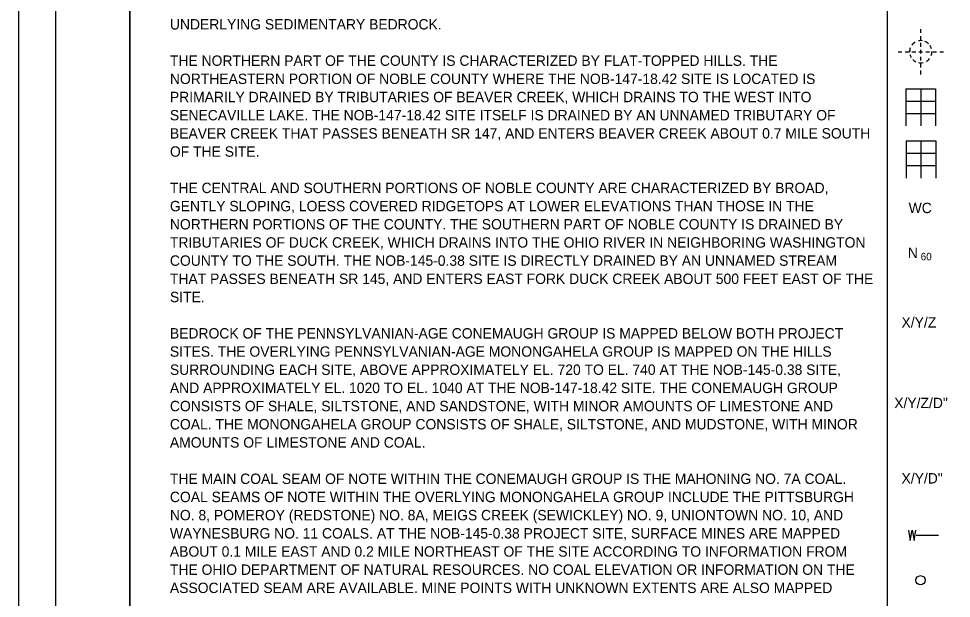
# Model space of a CAD drawing. Extents: x 0 to 34, y -8.9 to 22.
# Drawn here: x 0 to 12.57, y 6.5 to 14.31 of the extents above; entities that cross this region are included whole.
import ezdxf

# ---------------------------------------------------------------- set-up
doc = ezdxf.new("R2010")
doc.units = 0
for name, color, linetype in [('Default', 7, 'Continuous'), ('GT_Historic_Soil_Boring', 7, 'Continuous'), ('GT_Project_Cells', 7, 'Continuous'), ('GT_Project_Soil_Boring', 7, 'Continuous'), ('SH_Border', 7, 'Continuous'), ('SH_Cut_Line', 7, 'Continuous'), ('SH_Data', 7, 'Continuous'), ('SH_Text', 7, 'Continuous')]:
    doc.layers.add(name, color=color, linetype=linetype)

msp = doc.modelspace()

# ---------------------------------------------------------------- linework, layer by layer
at = {"layer": 'Default'}
for p, q in [((11.956, 12.663), (12.356, 12.663)), ((11.956, 12.663), (11.956, 12.163)), ((12.156, 12.663), (12.156, 12.163)), ((12.356, 12.663), (12.356, 12.163))]:
    msp.add_line(p, q, dxfattribs=at)
at = {"layer": 'GT_Historic_Soil_Boring'}
for p, q in [((12.154, 14.12), (12.154, 14.17)), ((12.154, 14.027), (12.154, 14.077)), ((12.154, 13.933), (12.154, 13.983)), ((11.849, 13.865), (11.899, 13.865)), ((11.943, 13.865), (11.993, 13.865)), ((12.036, 13.865), (12.086, 13.865)), ((12.129, 13.865), (12.179, 13.865)), ((12.154, 13.84), (12.154, 13.89)), ((12.223, 13.865), (12.273, 13.865)), ((12.316, 13.865), (12.366, 13.865)), ((12.409, 13.865), (12.459, 13.865)), ((12.154, 13.747), (12.154, 13.797)), ((12.154, 13.653), (12.154, 13.703)), ((12.154, 13.56), (12.154, 13.61))]:
    msp.add_line(p, q, dxfattribs=at)
for start, end in [(119.8468, 142.879), (80.7068, 102.4607), (46.3828, 68.4543), (160.0066, 182.1314), (194.7234, 210.6686), (15.179, 33.755), (339.9977, 1.8728), (224.4987, 243.6713), (257.8817, 281.9218), (300.6921, 322.0293)]:
    msp.add_arc((12.154, 13.865), 0.15, start, end, dxfattribs=at)
at = {"layer": 'GT_Project_Cells'}
msp.add_circle((12.151, 6.742), 0.0625, dxfattribs=at)
at = {"layer": 'GT_Project_Soil_Boring'}
for p, q in [((11.954, 13.365), (12.354, 13.365)), ((11.954, 13.365), (11.954, 12.865)), ((12.154, 13.365), (12.154, 12.865)), ((12.354, 13.365), (12.354, 12.865)), ((11.954, 13.198), (12.354, 13.198)), ((11.954, 13.032), (12.354, 13.032)), ((11.956, 12.497), (12.356, 12.497)), ((11.956, 12.33), (12.356, 12.33))]:
    msp.add_line(p, q, dxfattribs=at)
at = {"layer": 'SH_Border'}
for points in [[(0.5, 21.5), (1.5, 21.5), (1.5, 0.5), (0.5, 0.5)], [(1.5, 21.5), (33.5, 21.5), (33.5, 0.5), (1.5, 0.5)]]:
    msp.add_lwpolyline(points, close=True, dxfattribs=at)
at = {"layer": 'SH_Cut_Line'}
msp.add_lwpolyline([(0, 0), (34, 0), (34, 22), (0, 22)], close=True, dxfattribs=at)
at = {"layer": 'SH_Data'}
msp.add_line((11.705, 1.157), (11.705, 21.5), dxfattribs=at)
at = {"layer": 'SH_Text'}
msp.add_line((12.092, 7.349), (12.392, 7.349), dxfattribs=at)
msp.add_lwpolyline([(11.991, 7.419), (12.012, 7.279), (12.039, 7.419), (12.067, 7.279), (12.089, 7.419)], dxfattribs=at)

# ---------------------------------------------------------------- texts
at = {"layer": 'SH_Data'}
for s, height, p in [('WC', 0.14, (11.991, 11.69)), ('N', 0.14, (11.98, 11.085)), ('60', 0.1, (12.153, 11.055)), ('X/Y/Z', 0.14, (11.895, 10.147)), ('X/Y/Z/D"', 0.14, (11.797, 9.062)), ('X/Y/D"', 0.14, (11.895, 8.046))]:
    msp.add_text(s, height=height, dxfattribs=at).set_placement(p)
at = {"layer": 'SH_Text'}
for s, p in [('UNDERLYING SEDIMENTARY BEDROCK.', (2.038, 14.165)), ('THE NORTHERN PART OF THE COUNTY IS CHARACTERIZED BY FLAT-TOPPED HILLS. THE ', (2.038, 13.675)), ('NORTHEASTERN PORTION OF NOBLE COUNTY WHERE THE NOB-147-18.42 SITE IS LOCATED IS ', (2.038, 13.43)), ('PRIMARILY DRAINED BY TRIBUTARIES OF BEAVER CREEK, WHICH DRAINS TO THE WEST INTO ', (2.038, 13.185)), ('SENECAVILLE LAKE. THE NOB-147-18.42 SITE ITSELF IS DRAINED BY AN UNNAMED TRIBUTARY OF ', (2.038, 12.94)), ('BEAVER CREEK THAT PASSES BENEATH SR 147, AND ENTERS BEAVER CREEK ABOUT 0.7 MILE SOUTH ', (2.038, 12.695)), ('OF THE SITE.', (2.038, 12.45)), ('THE CENTRAL AND SOUTHERN PORTIONS OF NOBLE COUNTY ARE CHARACTERIZED BY BROAD, ', (2.038, 11.96)), ('GENTLY SLOPING, LOESS COVERED RIDGETOPS AT LOWER ELEVATIONS THAN THOSE IN THE ', (2.038, 11.715)), ('NORTHERN PORTIONS OF THE COUNTY. THE SOUTHERN PART OF NOBLE COUNTY IS DRAINED BY ', (2.038, 11.47)), ('TRIBUTARIES OF DUCK CREEK, WHICH DRAINS INTO THE OHIO RIVER IN NEIGHBORING WASHINGTON ', (2.038, 11.225)), ('COUNTY TO THE SOUTH. THE NOB-145-0.38 SITE IS DIRECTLY DRAINED BY AN UNNAMED STREAM ', (2.038, 10.98)), ('THAT PASSES BENEATH SR 145, AND ENTERS EAST FORK DUCK CREEK ABOUT 500 FEET EAST OF THE ', (2.038, 10.735)), ('SITE. ', (2.038, 10.49)), ('BEDROCK OF THE PENNSYLVANIAN-AGE CONEMAUGH GROUP IS MAPPED BELOW BOTH PROJECT ', (2.038, 10)), ('SITES. THE OVERLYING PENNSYLVANIAN-AGE MONONGAHELA GROUP IS MAPPED ON THE HILLS ', (2.038, 9.755)), ('SURROUNDING EACH SITE, ABOVE APPROXIMATELY EL. 720 TO EL. 740 AT THE NOB-145-0.38 SITE, ', (2.038, 9.51)), ('AND APPROXIMATELY EL. 1020 TO EL. 1040 AT THE NOB-147-18.42 SITE. THE CONEMAUGH GROUP ', (2.038, 9.265)), ('CONSISTS OF SHALE, SILTSTONE, AND SANDSTONE, WITH MINOR AMOUNTS OF LIMESTONE AND ', (2.038, 9.02)), ('COAL. THE MONONGAHELA GROUP CONSISTS OF SHALE, SILTSTONE, AND MUDSTONE, WITH MINOR ', (2.038, 8.775)), ('AMOUNTS OF LIMESTONE AND COAL.', (2.038, 8.53)), ('THE MAIN COAL SEAM OF NOTE WITHIN THE CONEMAUGH GROUP IS THE MAHONING NO. 7A COAL. ', (2.038, 8.04)), ('COAL SEAMS OF NOTE WITHIN THE OVERLYING MONONGAHELA GROUP INCLUDE THE PITTSBURGH ', (2.038, 7.795)), ('NO. 8, POMEROY (REDSTONE) NO. 8A, MEIGS CREEK (SEWICKLEY) NO. 9, UNIONTOWN NO. 10, AND ', (2.038, 7.55)), ('WAYNESBURG NO. 11 COALS. AT THE NOB-145-0.38 PROJECT SITE, SURFACE MINES ARE MAPPED ', (2.038, 7.305)), ('ABOUT 0.1 MILE EAST AND 0.2 MILE NORTHEAST OF THE SITE ACCORDING TO INFORMATION FROM ', (2.038, 7.06)), ('THE OHIO DEPARTMENT OF NATURAL RESOURCES. NO COAL ELEVATION OR INFORMATION ON THE ', (2.038, 6.815)), ('ASSOCIATED SEAM ARE AVAILABLE. MINE POINTS WITH UNKNOWN EXTENTS ARE ALSO MAPPED ', (2.038, 6.57))]:
    msp.add_text(s, height=0.14, dxfattribs=at).set_placement(p)

doc.saveas('drawing.dxf')
